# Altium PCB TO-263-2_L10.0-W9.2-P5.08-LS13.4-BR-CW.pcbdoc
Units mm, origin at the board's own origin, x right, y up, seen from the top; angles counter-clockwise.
Board outline 27.97 x 23 mm, 2 copper layers (Top Layer, Bottom Layer), stack 0.07 mm thick; 1 components, 0 nets, 3 pads, 0 vias.
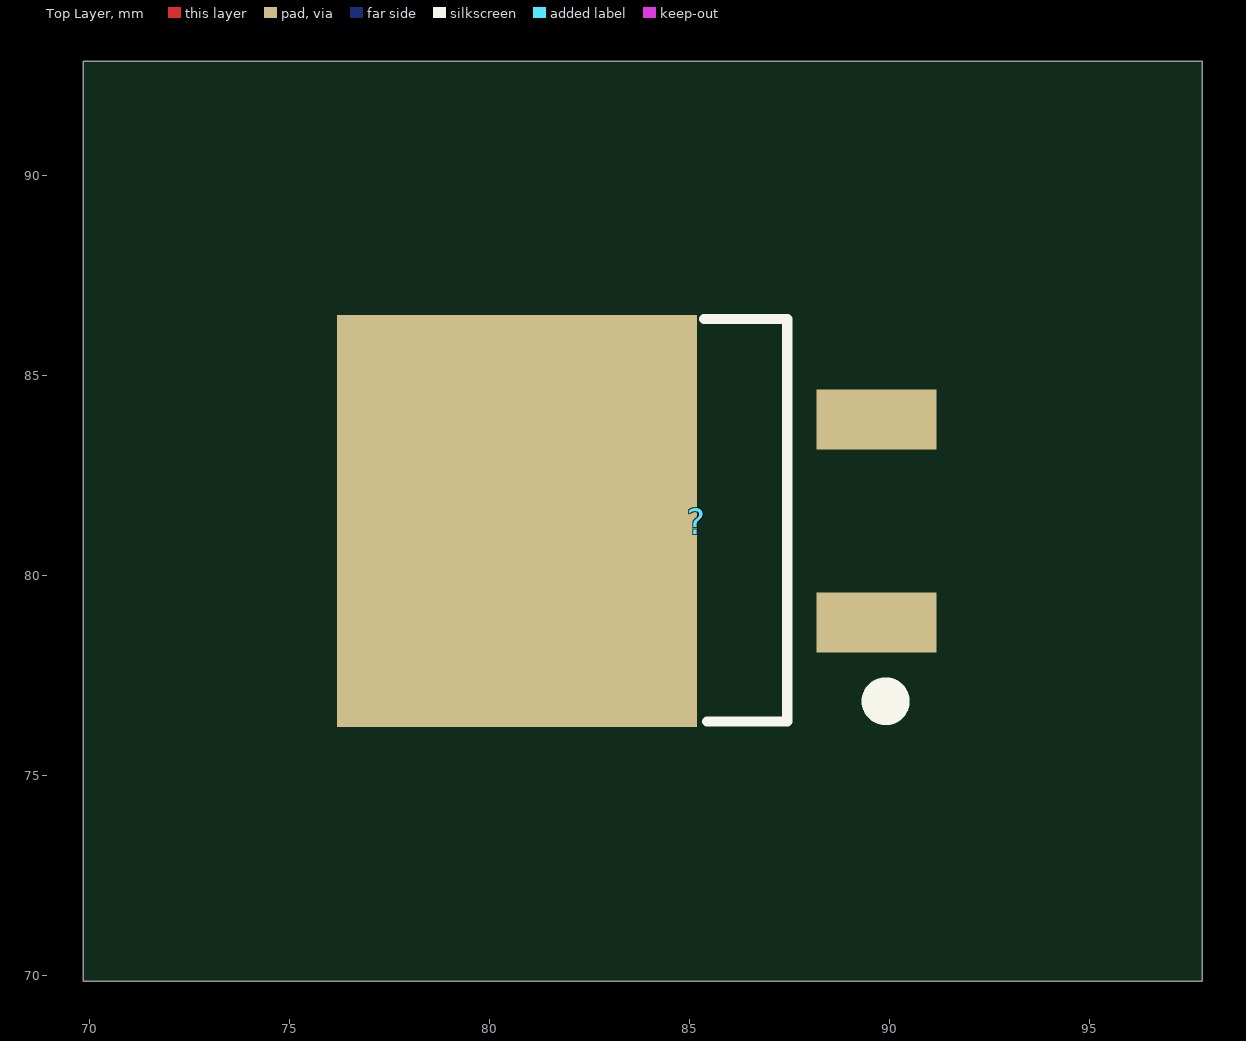
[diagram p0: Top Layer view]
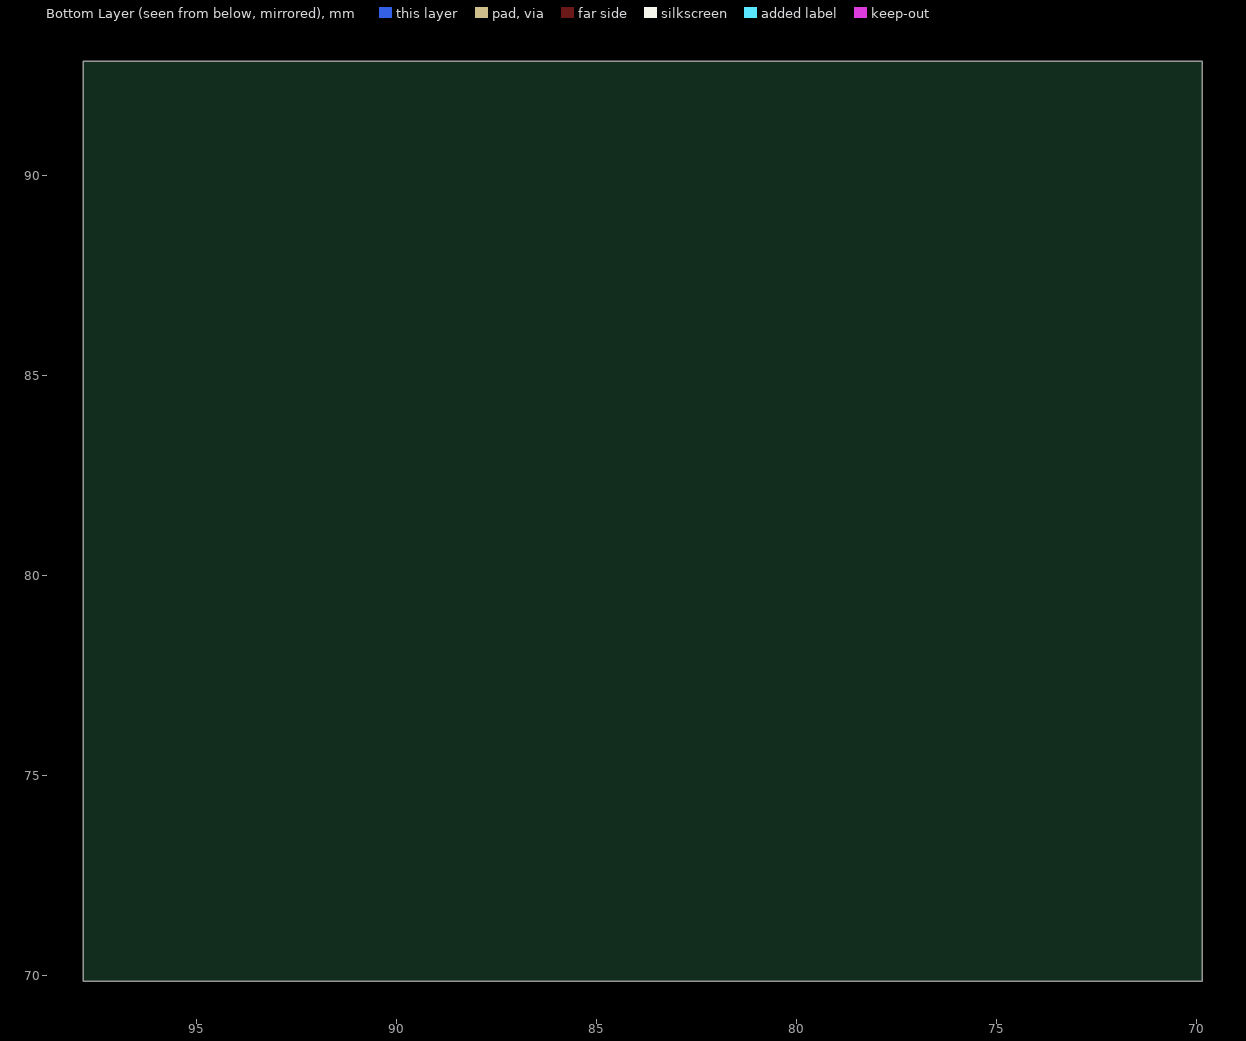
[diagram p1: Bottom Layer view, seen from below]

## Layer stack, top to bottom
Top Solder Mask Layer: solder mask 0.01, Dk 3.3
Top Layer: signal copper 0.035
Bottom Layer: signal copper 0.035
Bottom Solder Mask Layer: solder mask 0.01, Dk 3.3

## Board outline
97.823,69.85 69.85,69.85 69.85,92.85 97.823,92.85

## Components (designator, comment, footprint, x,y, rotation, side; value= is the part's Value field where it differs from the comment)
? "TO-263-2_L10.0-W9.2-P5.08-LS13.4-BR-CW" TO-263-2_L10.0-W9.2-P5.08-LS13.4-BR-CW 85.192,81.35 r0 top

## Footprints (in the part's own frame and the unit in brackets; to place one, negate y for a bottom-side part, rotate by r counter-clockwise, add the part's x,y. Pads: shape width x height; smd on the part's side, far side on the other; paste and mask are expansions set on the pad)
TO-263-2_L10.0-W9.2-P5.08-LS13.4-BR-CW [mm]
  rect 3x1.5 smd paste+0 mask+0.05: 1(4.492,-2.54) 3(4.492,2.54)
  rect 9x10.3 smd paste+0 mask+0.05: 2(-4.492,0)
  silkscreen extent 0.18,-5.01 5.02,5.05

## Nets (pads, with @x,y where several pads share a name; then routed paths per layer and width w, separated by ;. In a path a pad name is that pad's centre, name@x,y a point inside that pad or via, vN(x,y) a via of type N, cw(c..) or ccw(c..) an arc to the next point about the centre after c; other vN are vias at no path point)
pads on no net: ?.1 ?.2 ?.3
